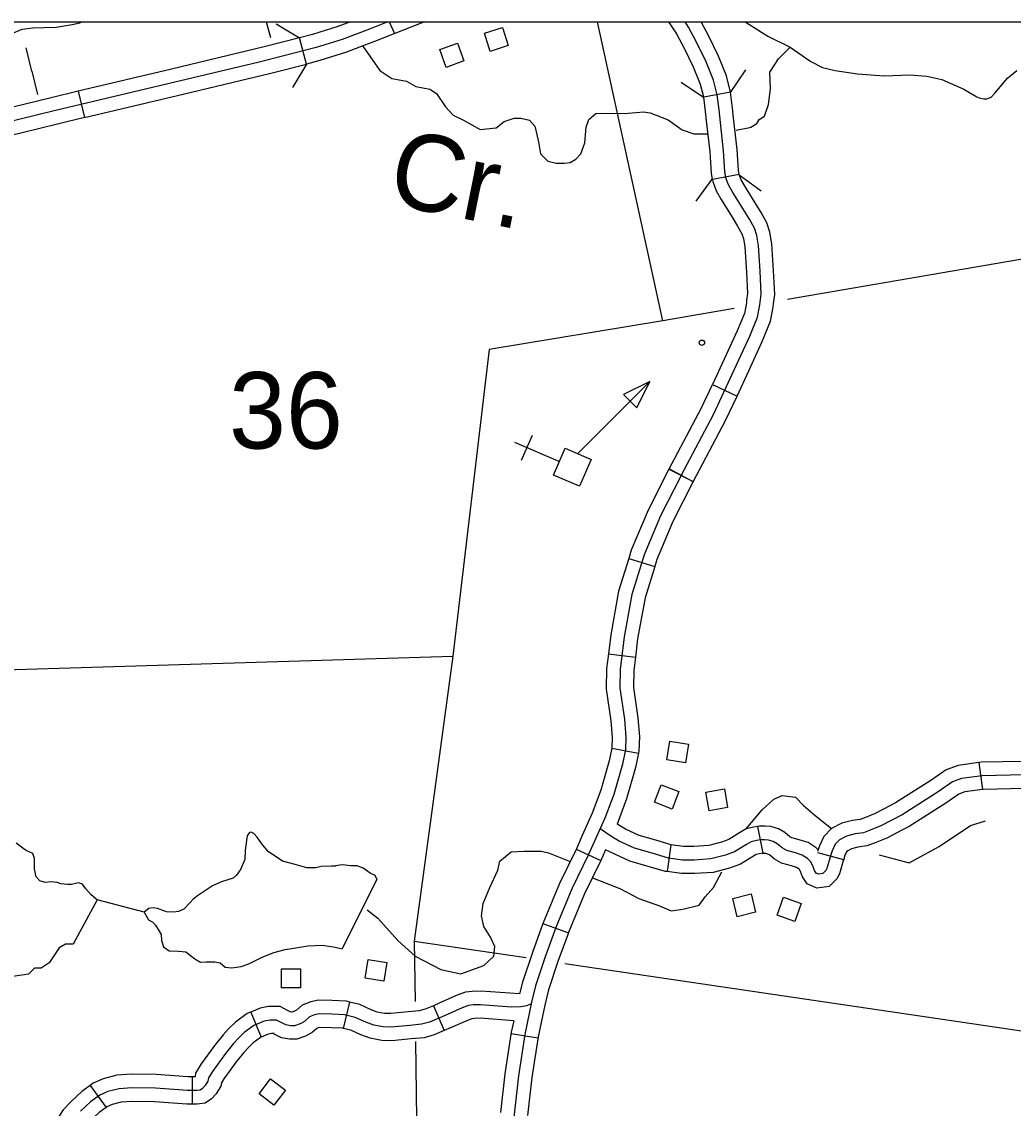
# Model space of a CAD drawing. Extents: x 155 to 3386, y 68 to 2138.
# Drawn here: x 2010 to 2166.4, y 1137.5 to 1309 of the extents above; entities that cross this region are included whole.
import ezdxf

# ---------------------------------------------------------------- set-up
doc = ezdxf.new("R2010")
doc.units = 0
for name, color, linetype in [('Default', 7, 'Continuous'), ('E_No Plot', 7, 'Continuous'), ('Level 31', 7, 'Continuous'), ('Level 32', 7, 'Continuous'), ('Level 35', 7, 'Continuous'), ('Level 38', 7, 'Continuous'), ('Level 4', 7, 'Continuous'), ('Level 40', 7, 'Continuous'), ('Level 43', 7, 'Continuous'), ('Level 45', 7, 'Continuous'), ('Level 5', 7, 'Continuous'), ('Level 56', 7, 'Continuous'), ('Level 57', 7, 'Continuous')]:
    doc.layers.add(name, color=color, linetype=linetype)

msp = doc.modelspace()

# ---------------------------------------------------------------- linework, layer by layer
at = {"layer": 'Default'}
msp.add_lwpolyline([(1150.5, 1308.99), (2342.15, 1308.99), (2342.15, 348.58), (1150.5, 348.58)], close=True, dxfattribs=at)
at = {"layer": 'E_No Plot'}
msp.add_lwpolyline([(1150.5, 1308.99), (2342.15, 1308.99), (2342.15, 348.58), (1150.5, 348.58)], close=True, dxfattribs=at)
msp.add_lwpolyline([(1150.5, 1308.99), (2342.15, 1308.99), (2342.15, 348.58), (1150.5, 348.58)], close=True, dxfattribs=at)
at = {"layer": 'Level 31'}
for p, q in [((2067.99, 1308.99), (2068.81, 1307.11)), ((2054.91, 1302.32), (2053.84, 1306.47)), ((2018.93, 1298.03), (2019.92, 1293.86)), ((2121.82, 1297.89), (2117.61, 1297.07)), ((2123.17, 1284.89), (2118.96, 1284.08)), ((2118.97, 1251.72), (2122.85, 1249.91)), ((2115.91, 1236.4), (2112.12, 1238.41))]:
    msp.add_line(p, q, dxfattribs=at)
for points in [[(2067.76, 1308.99), (2064.86, 1307.84), (2060.55, 1306.21), (2056.44, 1304.93), (2047.48, 1302.62), (2015.13, 1294.92), (1973.29, 1284.69), (1931.94, 1274.77)], [(2061.85, 1308.99), (2059.85, 1308.23), (2055.86, 1306.99), (2053.84, 1306.47)], [(2073.57, 1308.99), (2065.64, 1305.85), (2063.99, 1305.22)], [(2113.53, 1306.71), (2113.34, 1307.06), (2112.1, 1308.99)], [(2114.02, 1237.4), (2119.13, 1247.01), (2122.79, 1254.82), (2124.85, 1259.38), (2126.07, 1262.35), (2126.44, 1264.31), (2126.65, 1266), (2126.49, 1269.61), (2126.23, 1273.69), (2125.96, 1275.28), (2125.59, 1276.39), (2124.8, 1277.82), (2122.2, 1282.06), (2121.52, 1283.23), (2121.09, 1284.34), (2120.93, 1285.35), (2120.72, 1288.63), (2120.03, 1295.1), (2119.71, 1297.48), (2119.13, 1299.76), (2117.97, 1302.67), (2116.43, 1305.85), (2115.19, 1308.15), (2114.65, 1308.99)], [(2117.3, 1308.75), (2117.17, 1308.99)], [(2122.32, 1293.8), (2122.16, 1295.35), (2121.82, 1297.89), (2121.17, 1300.43), (2119.93, 1303.54), (2118.34, 1306.83), (2117.3, 1308.75)], [(2118.06, 1293.35), (2117.9, 1294.84), (2117.61, 1297.07), (2117.09, 1299.09), (2116, 1301.81), (2114.52, 1304.88), (2113.53, 1306.71)], [(2048.24, 1305.03), (2046.96, 1304.7), (2033.61, 1301.52)], [(2053.84, 1306.47), (2048.24, 1305.03)], [(2063.99, 1305.22), (2061.25, 1304.18), (2057.03, 1302.87), (2054.91, 1302.32)], [(2049.31, 1300.88), (2054.91, 1302.32)], [(2033.61, 1301.52), (2018.93, 1298.03)], [(2034.6, 1297.35), (2048, 1300.54), (2049.31, 1300.88)], [(2018.93, 1298.03), (2014.63, 1297), (2004.26, 1294.47)], [(2019.92, 1293.86), (2034.6, 1297.35)], [(2019.92, 1293.86), (2015.63, 1292.84), (2005.27, 1290.3)], [(2118.96, 1284.08), (2118.8, 1285.11), (2118.59, 1288.45), (2118.06, 1293.35)], [(2123.17, 1284.89), (2123.06, 1285.58), (2122.86, 1288.81), (2122.32, 1293.8)], [(2125.73, 1280.4), (2124.04, 1283.16), (2123.45, 1284.16), (2123.17, 1284.89)], [(2118.96, 1284.08), (2119.01, 1283.78), (2119.58, 1282.29), (2120.37, 1280.96), (2122.08, 1278.16)], [(2128.62, 1264.49), (2128.8, 1265.92), (2128.63, 1269.72), (2128.36, 1273.93), (2128.05, 1275.79), (2127.56, 1277.26), (2126.65, 1278.9), (2125.73, 1280.4)], [(2122.08, 1278.16), (2122.95, 1276.74), (2123.62, 1275.52), (2123.88, 1274.76), (2124.1, 1273.44), (2124.35, 1269.49), (2124.5, 1266.09), (2124.37, 1265.03)], [(2124.37, 1265.03), (2124.32, 1264.64), (2124.01, 1262.96), (2122.88, 1260.23), (2120.84, 1255.72), (2118.97, 1251.72)], [(2122.85, 1249.91), (2124.73, 1253.92), (2126.82, 1258.53), (2128.14, 1261.73), (2128.56, 1263.97), (2128.62, 1264.49)], [(2112.12, 1238.41), (2117.21, 1247.96), (2118.97, 1251.72)], [(2115.91, 1236.4), (2121.05, 1246.05), (2122.85, 1249.91)]]:
    msp.add_lwpolyline(points, dxfattribs=at)
at = {"layer": 'Level 32'}
for p, q in [((2112.1, 1238.37), (2115.93, 1236.43)), ((2105.78, 1224.3), (2109.87, 1223.03)), ((2102.56, 1209.21), (2106.81, 1208.69)), ((2103.09, 1194.36), (2107.3, 1193.53)), ((2126.1, 1181.97), (2126.94, 1177.77)), ((2097.47, 1178.39), (2101.38, 1176.64)), ((2112.41, 1179.1), (2111.81, 1174.86)), ((2135.53, 1177.9), (2139.66, 1176.75)), ((2092.24, 1166.66), (2096.26, 1165.18)), ((2061.72, 1154.28), (2060.71, 1150.11)), ((2046.15, 1152.7), (2047.8, 1148.75)), ((2074.95, 1153.7), (2076.63, 1149.76)), ((2091.43, 1148.6), (2087.2, 1149.24)), ((2036.89, 1142.47), (2036.89, 1138.18)), ((2020.8, 1141.12), (2023.32, 1137.65))]:
    msp.add_line(p, q, dxfattribs=at)
for points in [[(2112.1, 1238.37), (2108.84, 1231.93), (2106.17, 1225.57), (2105.78, 1224.3)], [(2114.02, 1237.4), (2110.79, 1231.03), (2108.19, 1224.84), (2106.26, 1218.6), (2105.05, 1211.92), (2104.42, 1206.76), (2104.37, 1203.8), (2105.09, 1198.91), (2105.32, 1196.08), (2105.23, 1194.11), (2104.78, 1191.82), (2103.39, 1187.02), (2102, 1183.29), (2099.44, 1177.55), (2096.79, 1172.12), (2094.28, 1166.02), (2092.58, 1161.4), (2091.05, 1156.82), (2090.43, 1154.26), (2089.35, 1149.15), (2088.36, 1142.64), (2086.57, 1126.67)], [(2115.93, 1236.43), (2112.73, 1230.13), (2110.2, 1224.11), (2109.87, 1223.03)], [(2105.78, 1224.3), (2104.17, 1219.11), (2102.93, 1212.24), (2102.56, 1209.21)], [(2109.87, 1223.03), (2108.34, 1218.09), (2107.17, 1211.6), (2106.81, 1208.69)], [(2102.56, 1209.21), (2102.28, 1206.9), (2102.23, 1203.66), (2102.96, 1198.67), (2103.17, 1196.04), (2103.09, 1194.36), (2103.09, 1194.36)], [(2106.81, 1208.69), (2106.56, 1206.61), (2106.52, 1203.94), (2107.22, 1199.15), (2107.46, 1196.12), (2107.36, 1193.85), (2107.3, 1193.53)], [(2103.09, 1194.36), (2102.69, 1192.32), (2101.35, 1187.69), (2100.01, 1184.1), (2098.44, 1180.56)], [(2107.3, 1193.53), (2106.86, 1191.31), (2105.42, 1186.34), (2103.94, 1182.36)], [(2137.6, 1177.33), (2137.04, 1175.35), (2136.86, 1175.04), (2136.38, 1174.55), (2135.75, 1174.46), (2135.35, 1174.63), (2135.09, 1175.04), (2134.82, 1175.75), (2134.46, 1176.46), (2133.98, 1176.95), (2133.13, 1177.48), (2132.06, 1177.84), (2130.69, 1178.19), (2129.98, 1178.59), (2129.18, 1179.26), (2128.55, 1179.62), (2127.8, 1179.84), (2127.22, 1179.88), (2126.6, 1179.88), (2125.93, 1179.75), (2125.09, 1179.57), (2124.33, 1179.13), (2122.46, 1177.97), (2121.04, 1177.48), (2118.73, 1176.86), (2116.11, 1176.68), (2114.24, 1176.68), (2112.02, 1176.99), (2109.44, 1177.75), (2106.69, 1178.55), (2104.24, 1179.66), (2103.09, 1180.37), (2101.24, 1181.6)], [(2112.47, 1179.09), (2110.04, 1179.8), (2107.43, 1180.56), (2105.25, 1181.55), (2103.94, 1182.36)], [(2126.1, 1181.97), (2125.5, 1181.85), (2124.3, 1181.6), (2123.22, 1180.96), (2121.54, 1179.92), (2120.41, 1179.53), (2118.38, 1178.98), (2116.04, 1178.82), (2114.39, 1178.82), (2112.41, 1179.1)], [(2135.65, 1178.31), (2135.32, 1178.63), (2134.06, 1179.43), (2132.67, 1179.89), (2131.49, 1180.2), (2131.2, 1180.36), (2130.4, 1181.03), (2129.4, 1181.6), (2128.19, 1181.96), (2127.3, 1182.02), (2126.39, 1182.02), (2126.1, 1181.97)], [(2098.44, 1180.56), (2097.5, 1178.45), (2094.84, 1173), (2092.29, 1166.8), (2092.24, 1166.66)], [(2102.11, 1178.28), (2101.38, 1176.64), (2098.75, 1171.24), (2096.28, 1165.24), (2096.26, 1165.18)], [(2111.81, 1174.86), (2111.57, 1174.89), (2108.84, 1175.69), (2105.94, 1176.53), (2102.11, 1178.28)], [(2126.94, 1177.77), (2126.36, 1177.65), (2125.87, 1177.55), (2125.44, 1177.29), (2123.39, 1176.02), (2121.67, 1175.43), (2119.09, 1174.73), (2116.18, 1174.54), (2114.09, 1174.54), (2111.81, 1174.86)], [(2139.66, 1176.75), (2139.03, 1174.51), (2138.58, 1173.72), (2137.39, 1172.53), (2135.45, 1172.25), (2133.91, 1172.93), (2133.17, 1174.05), (2132.85, 1174.89), (2132.7, 1175.19), (2132.63, 1175.26), (2132.21, 1175.53), (2131.46, 1175.78), (2129.88, 1176.19), (2128.75, 1176.82), (2127.95, 1177.49), (2127.71, 1177.63), (2127.41, 1177.72), (2127.14, 1177.74), (2126.81, 1177.74), (2126.94, 1177.77)], [(2092.24, 1166.66), (2090.56, 1162.11), (2088.99, 1157.41), (2088.54, 1155.55)], [(2096.26, 1165.18), (2094.6, 1160.69), (2093.11, 1156.22), (2092.52, 1153.79), (2091.95, 1151.07)], [(2088.54, 1155.55), (2082.41, 1156), (2081.06, 1155.95), (2080, 1155.82), (2078.71, 1155.35), (2075.97, 1154.14), (2074.95, 1153.7)], [(2061.72, 1154.28), (2061.23, 1154.4), (2059, 1154.5), (2056.8, 1154.55), (2055.59, 1154.33), (2054.26, 1153.79), (2053.36, 1152.99), (2053.03, 1152.81), (2052.66, 1152.68), (2052.64, 1152.68), (2052.36, 1152.73), (2052.04, 1152.88), (2050.78, 1153.59), (2049.81, 1153.59), (2048.96, 1153.59), (2047.64, 1153.32), (2046.15, 1152.7)], [(2074.95, 1153.7), (2073.64, 1153.15), (2072.68, 1152.87), (2071.01, 1152.71), (2068.24, 1152.45), (2067.26, 1152.49), (2066.09, 1152.7), (2065.12, 1153.06), (2063.32, 1153.89), (2061.72, 1154.28)], [(2090.37, 1153.99), (2089.71, 1153.68), (2088.75, 1153.54), (2087.25, 1153.49), (2082.38, 1153.86), (2081.24, 1153.81), (2080.51, 1153.72), (2079.51, 1153.36), (2076.82, 1152.17), (2074.36, 1151.12), (2073.09, 1150.76), (2071.22, 1150.58), (2068.3, 1150.3), (2067.03, 1150.35), (2065.53, 1150.62), (2064.3, 1151.08), (2062.61, 1151.85), (2060.93, 1152.26), (2058.92, 1152.36), (2056.96, 1152.4), (2056.19, 1152.26), (2055.42, 1151.95), (2054.6, 1151.22), (2053.91, 1150.85), (2053.05, 1150.53), (2052.45, 1150.53), (2051.68, 1150.67), (2051.04, 1150.99), (2050.22, 1151.44), (2049.81, 1151.44), (2049.18, 1151.44), (2048.27, 1151.26), (2046.63, 1150.58), (2045.12, 1149.48), (2044.21, 1148.57), (2043.44, 1147.71), (2042.16, 1146.16), (2040.11, 1143.33), (2039.48, 1142.29), (2039.38, 1141.78), (2038.97, 1141.1), (2038.52, 1140.64), (2038.15, 1140.37), (2037.61, 1140.33), (2036.15, 1140.33), (2031.1, 1140.69), (2027.36, 1140.74), (2025.36, 1140.6), (2023.58, 1140.14), (2022.35, 1139.6), (2020.85, 1138.5), (2019.3, 1137.05)], [(2046.15, 1152.7), (2045.57, 1152.46), (2043.73, 1151.12), (2042.65, 1150.05), (2041.81, 1149.1), (2040.47, 1147.47), (2038.33, 1144.52), (2037.44, 1143.06), (2037.35, 1142.55), (2037.3, 1142.47), (2036.89, 1142.47)], [(2087.62, 1151.32), (2082.34, 1151.71), (2081.41, 1151.68), (2081.01, 1151.63), (2080.31, 1151.37), (2077.67, 1150.21), (2076.63, 1149.76)], [(2087.62, 1151.32), (2087.24, 1149.53), (2086.24, 1142.92), (2085.55, 1136.83)], [(2091.95, 1151.07), (2091.46, 1148.77), (2090.49, 1142.36), (2089.81, 1136.36)], [(2060.71, 1150.11), (2060.62, 1150.13), (2058.85, 1150.21), (2057.13, 1150.25), (2056.79, 1150.19), (2056.57, 1150.1), (2055.83, 1149.45), (2054.79, 1148.89), (2053.43, 1148.39), (2052.27, 1148.39), (2051, 1148.61), (2050.04, 1149.09), (2049.67, 1149.3), (2049.81, 1149.3), (2049.39, 1149.3), (2048.89, 1149.2), (2047.8, 1148.75)], [(2076.63, 1149.76), (2075.08, 1149.1), (2073.49, 1148.65), (2071.42, 1148.45), (2068.37, 1148.16), (2066.8, 1148.21), (2064.96, 1148.55), (2063.48, 1149.1), (2061.9, 1149.82), (2060.71, 1150.11)], [(2047.8, 1148.75), (2047.68, 1148.7), (2046.52, 1147.85), (2045.77, 1147.1), (2045.06, 1146.31), (2043.86, 1144.85), (2041.9, 1142.15), (2041.51, 1141.51), (2041.42, 1141.02), (2040.68, 1139.77), (2039.93, 1139.02), (2038.95, 1138.29), (2037.7, 1138.18), (2036.89, 1138.18)], [(2036.89, 1142.47), (2036.23, 1142.47), (2031.19, 1142.83), (2027.3, 1142.88), (2025.02, 1142.72), (2022.87, 1142.17), (2021.27, 1141.46), (2020.8, 1141.12)], [(2020.8, 1141.12), (2019.48, 1140.16), (2017.79, 1138.57), (2016.52, 1137.24), (2015.02, 1134.92), (2013.53, 1131.93), (2012.52, 1128.72), (2012.16, 1127.6)], [(2023.32, 1137.65), (2022.22, 1136.85), (2020.81, 1135.52), (2019.9, 1134.57), (2018.75, 1132.79), (2017.51, 1130.32), (2016.61, 1127.42), (2016.24, 1126.28)], [(2036.89, 1138.18), (2036.07, 1138.18), (2031.01, 1138.55), (2027.42, 1138.59), (2025.7, 1138.47), (2024.29, 1138.11), (2023.43, 1137.73), (2023.32, 1137.65)]]:
    msp.add_lwpolyline(points, dxfattribs=at)
at = {"layer": 'Level 35'}
for points in [[(1991.28, 1301.73), (1992.44, 1302.06), (1995.62, 1302.06), (1998.68, 1303.37), (2000.06, 1304.31), (2000.81, 1305.06), (2001.8, 1305.62), (2002.99, 1305.62), (2004.3, 1305.62), (2006.55, 1306.37), (2010.05, 1307.81), (2011.68, 1308.03), (2015.42, 1308.16), (2017.98, 1308.53), (2019.17, 1308.84), (2019.49, 1308.99)], [(2124.15, 1308.99), (2127.71, 1306.72), (2131.21, 1305), (2134.51, 1302.72), (2136.35, 1301.76), (2138.32, 1301.32), (2141.84, 1300.78), (2146.06, 1300.46), (2150.09, 1300.59), (2152.79, 1300.4), (2155.18, 1299.86), (2158.64, 1298.33), (2160.68, 1297.13), (2161.21, 1296.94), (2161.79, 1296.84), (2162.26, 1296.84), (2162.93, 1297.09), (2163.53, 1297.7), (2165.5, 1300.08), (2166.99, 1301.32)], [(2063.82, 1305.16), (2066.5, 1301.28), (2068.38, 1300.02), (2070.7, 1299.62), (2072.2, 1298.75), (2074.38, 1298.37), (2075.44, 1297.68), (2076.88, 1295.56), (2078.07, 1294.25), (2079.69, 1293.44), (2082.31, 1292), (2084.87, 1292.25)], [(2122.69, 1291.9), (2124.87, 1292.28), (2125.04, 1292.37), (2125.98, 1292.94), (2126.35, 1293.56), (2127.17, 1294.08), (2127.84, 1295.92), (2128.14, 1298.39), (2128.05, 1301.03), (2129.39, 1303.13), (2131.21, 1305)], [(2084.87, 1292.25), (2086.12, 1293.25), (2087.68, 1293.75), (2088.74, 1293.75), (2090.11, 1293.44), (2090.93, 1292.5), (2091.55, 1290.06), (2091.86, 1288.13), (2092.99, 1287), (2094.3, 1286.69), (2095.61, 1286.69), (2096.55, 1286.75), (2097.42, 1287.31), (2098.23, 1288.13), (2098.86, 1289.88), (2099.04, 1292.37), (2099.48, 1293.56), (2100.6, 1294.5), (2102.23, 1294.56), (2105.1, 1294.5), (2108.1, 1294.75), (2109.16, 1294.62), (2111.97, 1293.5), (2114.21, 1291.94), (2116.02, 1291.31), (2117.71, 1291.31), (2118.21, 1291.31)], [(2124.3, 1181.6), (2126.83, 1184.62), (2128.66, 1186.32), (2129.96, 1186.85), (2132.05, 1186.59), (2133.36, 1185.28), (2135.19, 1183.71), (2137.75, 1181.64)], [(2066.05, 1173.65), (2065.76, 1174.23), (2064.97, 1174.64), (2063.86, 1175.38), (2062.91, 1175.79), (2061.92, 1175.79), (2060.56, 1175.92), (2059.53, 1175.75), (2059.49, 1175.71), (2058.87, 1175.71), (2057.26, 1175.67), (2056.4, 1175.46), (2054.96, 1175.46), (2053.14, 1175.96), (2051.12, 1176.53), (2048.9, 1178.02), (2047.91, 1179.26), (2047.17, 1180.29), (2046.63, 1180.86), (2046.22, 1181.11), (2045.93, 1181.03), (2045.56, 1180.49), (2045.23, 1178.27), (2045.19, 1176.78), (2044.53, 1175.17), (2043.87, 1174.31), (2043.38, 1173.85), (2041.52, 1173.24), (2040.08, 1172.62), (2037.73, 1171.05), (2037.03, 1170.51), (2036.57, 1169.98), (2035.59, 1168.91), (2034.76, 1168.58), (2033.94, 1168.45), (2032.82, 1168.49), (2031.42, 1169.03), (2030.76, 1169.15), (2030.06, 1169.03), (2029.32, 1168.45), (2030.02, 1167.26), (2030.68, 1166.89), (2031.09, 1166.43), (2031.71, 1165.48), (2032, 1164.95), (2032.04, 1164), (2032.37, 1163.01), (2033.28, 1162.35), (2034.72, 1162.31), (2035.87, 1162.18), (2037.32, 1161.07), (2038.22, 1160.58), (2039.09, 1160.62), (2040.45, 1160.62), (2041.31, 1160.45), (2042.1, 1159.79), (2043.13, 1159.67), (2044.61, 1159.88), (2045.81, 1160.33), (2047.83, 1161.28), (2049.8, 1162.1), (2051.54, 1162.56), (2053.27, 1162.84), (2055.16, 1163.13), (2057.47, 1163.26), (2059.45, 1162.93), (2060.56, 1162.67)], [(2029.32, 1168.45), (2021.93, 1170.42), (2021.73, 1170.52), (2020.89, 1171.23), (2020.11, 1172.13), (2019.6, 1172.87), (2018.95, 1173.1), (2017.85, 1172.84), (2017.24, 1172.81), (2016.17, 1172.94), (2015.59, 1173.16), (2014.66, 1173.23), (2013.69, 1173.16), (2012.88, 1173.39), (2012.27, 1174.04), (2012.04, 1175.26), (2012.04, 1176.94), (2011.75, 1177.72), (2010.59, 1178.27), (2009.14, 1179.36)], [(2064.5, 1168.81), (2066.2, 1167.5), (2069.33, 1163.97), (2072.08, 1161.49), (2076.13, 1159.4), (2079.26, 1158.74), (2082.92, 1160.05), (2084.49, 1161.49), (2084.62, 1163.06), (2083.97, 1164.49), (2082.92, 1166.19), (2082.53, 1167.89), (2082.79, 1169.85), (2083.84, 1172.34), (2085.14, 1175.08), (2085.41, 1176.52), (2087.24, 1177.96), (2089.2, 1178.09), (2091.94, 1178.09), (2093.12, 1177.83), (2096.53, 1176.46)], [(2100.05, 1173.9), (2104.35, 1172.21), (2107.36, 1170.64), (2110.63, 1169.46), (2112.45, 1168.68), (2114.28, 1168.94), (2116.9, 1169.59), (2117.81, 1170.9), (2119.12, 1172.34), (2120.43, 1174.82)], [(2066.05, 1173.65), (2060.56, 1162.67)], [(2021.93, 1170.42), (2018.11, 1163.43), (2016.9, 1163.43), (2015.93, 1162.85), (2014.32, 1160.46), (2013.09, 1159.62), (2012, 1159.62), (2011.09, 1158.65)], [(2011.09, 1158.65), (2005.72, 1157.9), (2003.43, 1156.05), (2002.29, 1154.19), (2001, 1153.9), (2000.29, 1154.05), (1998.86, 1155.62), (1998, 1156.9), (1996.72, 1157.48), (1992.72, 1157.05), (1987.29, 1155.33), (1983.72, 1153.05), (1982.32, 1152.63)]]:
    msp.add_lwpolyline(points, dxfattribs=at)
at = {"layer": 'Level 38'}
for points in [[(2050.15, 1308.65), (2053.84, 1306.47)], [(2054.91, 1302.32), (2052.73, 1298.63)], [(2124.18, 1301.39), (2121.78, 1297.84)], [(2117.58, 1297.02), (2114.02, 1299.42)], [(2123.18, 1284.82), (2126.65, 1282.3)], [(2116.43, 1280.68), (2118.95, 1284.15)]]:
    msp.add_lwpolyline(points, dxfattribs=at)
at = {"layer": 'Level 4'}
msp.add_lwpolyline([(1953.77, 1205.36), (2007.28, 1206.73), (2078, 1208.85)], dxfattribs=at)
at = {"layer": 'Level 40'}
for p, q in [((2048.56, 1308.99), (2049.25, 1306.5)), ((2011.61, 1301.19), (2010.73, 1304.86)), ((2011.61, 1301.19), (2012.5, 1297.52))]:
    msp.add_line(p, q, dxfattribs=at)
at = {"layer": 'Level 43'}
msp.add_lwpolyline([(2145.29, 1177.5), (2150.02, 1176.26), (2154.72, 1178.82), (2159.69, 1182.12), (2162.05, 1182.85)], dxfattribs=at)
at = {"layer": 'Level 45'}
msp.add_line((2160.98, 1192.07), (2161.57, 1187.82), dxfattribs=at)
for points in [[(2160.98, 1192.07), (2157.76, 1191.62), (2155.87, 1190.93), (2153.42, 1189.25), (2147.85, 1185.7), (2146.98, 1185.25)], [(2176.02, 1192.84), (2175.04, 1192.69), (2168.07, 1192.25), (2161.34, 1192.12), (2160.98, 1192.07)], [(2168.16, 1190.11), (2161.51, 1189.98), (2158.28, 1189.53), (2156.86, 1189.01), (2154.6, 1187.46), (2148.92, 1183.84), (2145.56, 1182.1), (2143.88, 1181.39), (2142.79, 1181), (2141.5, 1180.81), (2140.14, 1180.48), (2139.04, 1179.9), (2138.33, 1179.19), (2137.88, 1178.16), (2137.6, 1177.33)], [(2176.64, 1188.59), (2175.48, 1188.43), (2168.25, 1187.97), (2161.68, 1187.84), (2161.57, 1187.82)], [(2161.57, 1187.82), (2158.8, 1187.43), (2157.85, 1187.09), (2155.78, 1185.67), (2149.99, 1181.98), (2148.95, 1181.44)], [(2146.98, 1185.25), (2144.65, 1184.04), (2143.11, 1183.39), (2142.27, 1183.09), (2141.09, 1182.91), (2139.38, 1182.5), (2137.75, 1181.64), (2136.53, 1180.42), (2135.88, 1178.93), (2135.57, 1178.01)], [(2148.95, 1181.44), (2146.48, 1180.16), (2144.66, 1179.39), (2143.31, 1178.91), (2141.9, 1178.7), (2140.9, 1178.46), (2140.33, 1178.16), (2140.13, 1177.96), (2139.88, 1177.38), (2139.63, 1176.64)]]:
    msp.add_lwpolyline(points, dxfattribs=at)
at = {"layer": 'Level 5'}
for points in [[(2111.13, 1261.79), (2100.83, 1308.99)], [(2248.39, 1285.33), (2130.82, 1265.17)], [(2122.38, 1263.72), (2111.13, 1261.79)], [(2111.13, 1261.79), (2083.77, 1257.25)], [(2083.77, 1257.25), (2078, 1208.85)], [(2078, 1208.85), (2071.93, 1163.89)], [(2071.93, 1163.89), (2072.05, 1154.38)], [(2071.93, 1163.89), (2089.57, 1161.28)], [(2095.69, 1160.38), (2222.31, 1141.66)], [(2072.13, 1148.03), (2072.75, 1099.02)]]:
    msp.add_lwpolyline(points, dxfattribs=at)
at = {"layer": 'Level 56'}
for points in [[(2083, 1307.17), (2085.84, 1308.07), (2086.74, 1305.22), (2083.91, 1304.32)], [(2075.96, 1304.59), (2078.75, 1305.61), (2079.77, 1302.8), (2076.97, 1301.79)], [(2112.27, 1195.44), (2115.2, 1194.95), (2114.7, 1192.01), (2111.77, 1192.5)], [(2109.82, 1185.8), (2110.9, 1188.57), (2113.68, 1187.48), (2112.6, 1184.71)], [(2120.85, 1187.9), (2121.37, 1184.97), (2118.43, 1184.45), (2117.91, 1187.38)], [(2122.89, 1167.74), (2122.17, 1170.63), (2125.06, 1171.35), (2125.78, 1168.47)], [(2129.16, 1168.01), (2130.16, 1170.81), (2132.97, 1169.81), (2131.97, 1167.01)], [(2064.67, 1160.98), (2067.61, 1160.51), (2067.14, 1157.57), (2064.2, 1158.03)], [(2051, 1156.54), (2051, 1159.52), (2053.98, 1159.52), (2053.98, 1156.54)], [(2049.26, 1142.17), (2051.62, 1140.36), (2049.8, 1138), (2047.44, 1139.81)]]:
    msp.add_lwpolyline(points, close=True, dxfattribs=at)
at = {"layer": 'Level 57'}
for p, q in [((2088.87, 1239.82), (2090.57, 1243.75)), ((2087.76, 1242.64), (2094.82, 1239.58))]:
    msp.add_line(p, q, dxfattribs=at)
msp.add_lwpolyline([(2109.08, 1252.2), (2097.8, 1240.92)], dxfattribs=at)
for points in [[(2104.96, 1250.14), (2107.02, 1248.08), (2109.08, 1252.2)], [(2097.98, 1235.68), (2093.89, 1237.45), (2095.73, 1241.7), (2099.82, 1239.92)]]:
    msp.add_lwpolyline(points, close=True, dxfattribs=at)
msp.add_circle((2117.3, 1258.33), 0.429, dxfattribs=at)

# ---------------------------------------------------------------- texts
at = {"layer": 'Level 43'}
msp.add_text('Cr.', height=12.069, rotation=348.6842, dxfattribs=at).set_placement((2067.39, 1280.36))
at = {"layer": 'Level 5'}
msp.add_text('36', height=12.069, dxfattribs=at).set_placement((2042.71, 1241.63))

doc.saveas('drawing.dxf')
